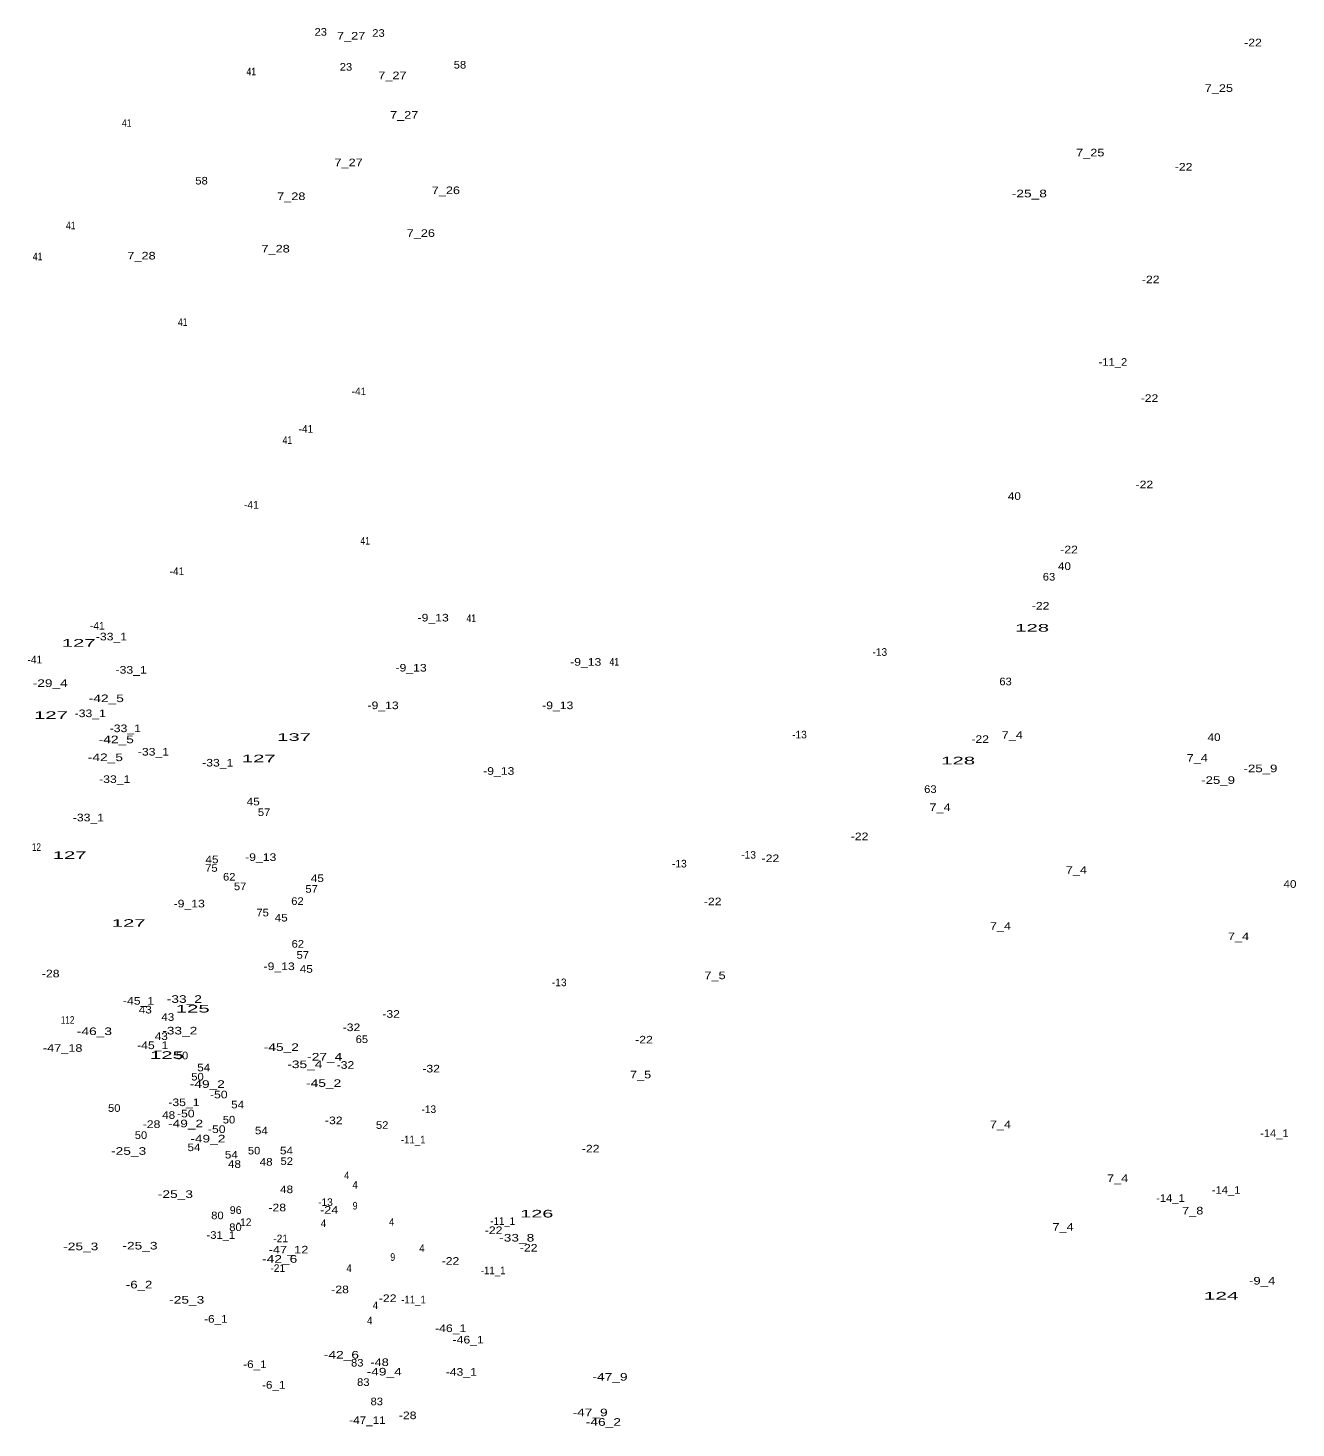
# Model space of a CAD drawing. Extents: x -663705 to -661666, y -1002081 to -999269.
# Drawn here: x -663123 to -662455, y -1001333 to -1000597 of the extents above; entities that cross this region are included whole.
import ezdxf
from ezdxf.enums import TextEntityAlignment as Align

# ---------------------------------------------------------------- set-up
doc = ezdxf.new("R2010")
doc.units = 0
doc.header["$LTSCALE"] = 1.6
doc.layers.add('24', color=7, linetype='Continuous')

msp = doc.modelspace()

# ---------------------------------------------------------------- texts
at = {"layer": '24'}
for s, width, p in [('23', 1.1, (-662968.579, -1000601.17)), ('7_27', 1.25, (-662952.58, -1000603.18)), ('23', 1.1, (-662938.199, -1000601.75)), ('-22', 1.2, (-662478.09, -1000606.76)), ('23', 1.1, (-662955.309, -1000619.54)), ('58', 1.1, (-662895.34, -1000618.45)), ('41', 0.85, (-663005.11, -1000622)), ('7_27', 1.25, (-662930.86, -1000624.04)), ('7_25', 1.25, (-662496.069, -1000630.71)), ('41', 0.85, (-663070.63, -1000649.08)), ('7_27', 1.25, (-662924.66, -1000644.8)), ('7_25', 1.25, (-662563.73, -1000664.65)), ('7_27', 1.25, (-662953.93, -1000669.81)), ('-22', 1.2, (-662514.61, -1000672.14)), ('58', 1.1, (-663031.28, -1000679.42)), ('7_26', 1.25, (-662902.75, -1000684.48)), ('-25_8', 1.35, (-662595.78, -1000686.17)), ('7_28', 1.25, (-662984.079, -1000687.61)), ('41', 0.85, (-663100.1, -1000702.99)), ('7_26', 1.25, (-662915.93, -1000706.98)), ('7_28', 1.25, (-662992.319, -1000715.18)), ('41', 0.85, (-663117.549, -1000719.28)), ('7_28', 1.25, (-663062.88, -1000718.86)), ('-22', 1.2, (-662531.91, -1000731.37)), ('41', 0.85, (-663041.169, -1000753.8)), ('-11_2', 1.1, (-662551.799, -1000774.76)), ('-22', 1.2, (-662532.57, -1000793.8)), ('41', 0.85, (-662986.11, -1000815.86)), ('-22', 1.2, (-662535.26, -1000839.19)), ('40', 1.15, (-662603.669, -1000845.32)), ('41', 0.85, (-662945.199, -1000868.82)), ('-22', 1.2, (-662574.86, -1000873.42)), ('40', 1.15, (-662577.309, -1000882.17)), ('63', 1.1, (-662585.42, -1000887.73)), ('-22', 1.2, (-662589.85, -1000903.03)), ('-9_13', 1.2, (-662909.431, -1000909.26)), ('41', 0.85, (-662889.37, -1000909.55)), ('128', 2, (-662594.297, -1000914.61)), ('127', 2, (-663095.913, -1000922.52)), ('-33_1', 1.2, (-663078.699, -1000919.2)), ('-33_1', 1.2, (-663068.319, -1000936.7)), ('-9_13', 1.2, (-662921.061, -1000935.6)), ('-9_13', 1.2, (-662829.171, -1000932.53)), ('41', 0.85, (-662814.15, -1000932.44)), ('-29_4', 1.35, (-663110.91, -1000943.69)), ('63', 1.1, (-662608.29, -1000942.81)), ('-42_5', 1.35, (-663081.39, -1000951.68)), ('-33_1', 1.2, (-663089.85, -1000959.58)), ('-9_13', 1.2, (-662935.791, -1000955.38)), ('-9_13', 1.2, (-662843.9, -1000955.38)), ('127', 2, (-663110.493, -1000960.51)), ('-42_5', 1.35, (-663076.16, -1000973.3)), ('-33_1', 1.2, (-663071.4, -1000967.47)), ('137', 2, (-662982.623, -1000972.05)), ('-22', 1.2, (-662621.65, -1000973.15)), ('7_4', 1.25, (-662604.77, -1000970.99)), ('40', 1.15, (-662498.6, -1000972.15)), ('-33_1', 1.2, (-663056.6, -1000979.78)), ('-42_5', 1.35, (-663081.88, -1000982.71)), ('-33_1', 1.2, (-663022.76, -1000985.55)), ('127', 2, (-663001.173, -1000983.34)), ('128', 2, (-662633.227, -1000984.44)), ('7_4', 1.25, (-662507.44, -1000983.01)), ('-25_9', 1.3, (-662474.17, -1000988.55)), ('-33_1', 1.2, (-663076.97, -1000994.2)), ('-9_13', 1.2, (-662874.921, -1000989.9)), ('-25_9', 1.3, (-662496.47, -1000994.71)), ('63', 1.1, (-662647.84, -1000999.44)), ('45', 1.15, (-663004.1, -1001005.98)), ('7_4', 1.25, (-662642.76, -1001009)), ('-33_1', 1.2, (-663090.809, -1001014.39)), ('57', 1.1, (-662998.39, -1001011.6)), ('-22', 1.2, (-662685.09, -1001024.3)), ('12', 0.8, (-663118.169, -1001029.94)), ('127', 2, (-663100.713, -1001034.18)), ('45', 1.15, (-663025.809, -1001036.43)), ('-9_13', 1.2, (-663000.16, -1001035.22)), ('-22', 1.2, (-662731.99, -1001035.84)), ('75', 1.1, (-663026.1, -1001040.92)), ('62', 1.1, (-663016.71, -1001045.54)), ('45', 1.15, (-662970.37, -1001046.32)), ('7_4', 1.25, (-662571.03, -1001041.97)), ('57', 1.1, (-663010.99, -1001050.58)), ('57', 1.1, (-662973.38, -1001051.94)), ('40', 1.15, (-662458.66, -1001049.34)), ('-9_13', 1.2, (-663037.77, -1001059.65)), ('62', 1.1, (-662980.84, -1001058.34)), ('-22', 1.2, (-662762.37, -1001058.53)), ('127', 2, (-663069.643, -1001069.87)), ('75', 1.1, (-662999.16, -1001064.39)), ('45', 1.15, (-662989.37, -1001067.07)), ('7_4', 1.25, (-662610.97, -1001071.45)), ('7_4', 1.25, (-662485.73, -1001076.88)), ('62', 1.1, (-662980.65, -1001080.84)), ('57', 1.1, (-662978.03, -1001086.66)), ('-28', 1.2, (-663110.65, -1001096.44)), ('-9_13', 1.2, (-662990.461, -1001092.62)), ('45', 1.15, (-662976.179, -1001094.03)), ('7_5', 1.25, (-662761.15, -1001097.41)), ('-45_1', 1.2, (-663064.439, -1001110.81)), ('-33_2', 1.35, (-663040.34, -1001109.85)), ('112', 0.8, (-663101.77, -1001120.88)), ('43', 1.15, (-663060.89, -1001115.44)), ('43', 1.15, (-663049.059, -1001119.32)), ('125', 2, (-663035.907, -1001114.94)), ('-32', 1.2, (-662931.55, -1001117.71)), ('-46_3', 1.35, (-663087.65, -1001126.8)), ('-33_2', 1.35, (-663042.74, -1001126.48)), ('-32', 1.2, (-662952.41, -1001124.73)), ('-47_18', 1.25, (-663104.36, -1001135.62)), ('-45_1', 1.2, (-663056.98, -1001134.18)), ('43', 1.15, (-663052.449, -1001129.4)), ('-45_2', 1.35, (-662989.33, -1001135.15)), ('65', 1.1, (-662946.95, -1001130.99)), ('-22', 1.2, (-662798.51, -1001131.23)), ('125', 2, (-663049.517, -1001139.31)), ('50', 1.1, (-663041.559, -1001139.55)), ('-27_4', 1.35, (-662966.47, -1001140.21)), ('50', 1.1, (-663033.419, -1001150.71)), ('54', 1.15, (-663030.13, -1001145.85)), ('-35_4', 1.35, (-662976.95, -1001144.19)), ('-32', 1.2, (-662955.58, -1001144.54)), ('-32', 1.2, (-662910.5, -1001146.46)), ('7_5', 1.25, (-662800.309, -1001149.58)), ('-49_2', 1.35, (-663028.26, -1001154.57)), ('-45_2', 1.35, (-662967.04, -1001154.06)), ('-35_1', 1.2, (-663040.569, -1001164.17)), ('-50', 1.2, (-663022.22, -1001160.08)), ('54', 1.15, (-663012.299, -1001165.34)), ('50', 1.1, (-663077.209, -1001167.19)), ('48', 1.15, (-663048.6, -1001170.87)), ('-50', 1.2, (-663039.58, -1001170.07)), ('50', 1.1, (-663016.84, -1001173.3)), ('-28', 1.2, (-663057.59, -1001175.68)), ('-49_2', 1.35, (-663039.7, -1001175.32)), ('-50', 1.2, (-663023.29, -1001178.31)), ('54', 1.15, (-662999.79, -1001179.01)), ('-32', 1.2, (-662961.73, -1001173.67)), ('52', 1.1, (-662936.26, -1001176.12)), ('7_4', 1.25, (-662610.97, -1001175.79)), ('-14_1', 1.1, (-662466.88, -1001180.42)), ('50', 1.1, (-663063.15, -1001181.44)), ('54', 1.15, (-663035.27, -1001187.84)), ('-49_2', 1.35, (-663027.97, -1001183.27)), ('-11_1', 0.95, (-662919.95, -1001183.76)), ('-25_3', 1.35, (-663069.65, -1001189.78)), ('54', 1.15, (-663015.59, -1001191.71)), ('50', 1.1, (-663003.66, -1001189.59)), ('54', 1.15, (-662986.61, -1001189.58)), ('52', 1.1, (-662986.48, -1001195.12)), ('-22', 1.2, (-662826.57, -1001188.53)), ('48', 1.15, (-663013.98, -1001196.66)), ('48', 1.15, (-662997.309, -1001195.5)), ('4', 0.95, (-662954.929, -1001202.59)), ('48', 1.15, (-662986.549, -1001209.95)), ('4', 0.95, (-662950.5, -1001207.59)), ('7_4', 1.25, (-662549.32, -1001204.1)), ('-25_3', 1.35, (-663045.04, -1001212.47)), ('-14_1', 1.1, (-662521.549, -1001214.55)), ('-14_1', 1.1, (-662492.27, -1001210.28)), ('80', 1.1, (-663022.939, -1001223.66)), ('96', 1.05, (-663013.35, -1001220.85)), ('-28', 1.2, (-662991.46, -1001219.52)), ('-24', 1.25, (-662964.16, -1001220.79)), ('9', 0.85, (-662950.51, -1001218.53)), ('126', 1.95, (-662854.913, -1001222.75)), ('7_8', 1.25, (-662509.819, -1001221.16)), ('80', 1.1, (-663013.449, -1001229.87)), ('4', 0.95, (-662967.13, -1001227.79)), ('4', 0.95, (-662931.28, -1001227.11)), ('-22', 1.2, (-662877.63, -1001231.46)), ('-11_1', 0.95, (-662872.84, -1001226.62)), ('7_4', 1.25, (-662578.01, -1001229.7)), ('-25_3', 1.35, (-663063.689, -1001239.58)), ('-31_1', 1.1, (-663021.12, -1001233.98)), ('-33_8', 1.35, (-662865.47, -1001235.4)), ('-25_3', 1.35, (-663094.829, -1001239.96)), ('-42_6', 1.35, (-662990.17, -1001246.56)), ('-47_12', 1.25, (-662985.53, -1001241.67)), ('9', 0.85, (-662930.71, -1001245.55)), ('4', 0.95, (-662915.329, -1001240.86)), ('-22', 1.2, (-662859.18, -1001240.69)), ('4', 0.95, (-662953.669, -1001251.43)), ('-22', 1.2, (-662900.32, -1001247.61)), ('-11_1', 0.95, (-662877.88, -1001252.59)), ('-6_2', 1.3, (-663064.14, -1001260.05)), ('-9_4', 1.3, (-662473.28, -1001258.02)), ('-25_3', 1.35, (-663039.079, -1001268.04)), ('-28', 1.2, (-662958.4, -1001262.6)), ('-22', 1.2, (-662933.38, -1001267.23)), ('-11_1', 0.95, (-662919.76, -1001267.91)), ('124', 2.05, (-662494.833, -1001265.89)), ('4', 0.95, (-662939.84, -1001270.96)), ('-6_1', 1.15, (-663023.75, -1001278.08)), ('4', 0.95, (-662942.809, -1001278.95)), ('-46_1', 1.2, (-662900.22, -1001283.02)), ('-46_1', 1.2, (-662891.01, -1001289.03)), ('-42_6', 1.35, (-662957.7, -1001296.96)), ('-6_1', 1.15, (-663003.201, -1001301.93)), ('83', 1.1, (-662949.38, -1001301.15)), ('-49_4', 1.35, (-662935.189, -1001305.84)), ('-48', 1.25, (-662937.62, -1001300.89)), ('-6_1', 1.15, (-662993.311, -1001312.79)), ('83', 1.1, (-662946.189, -1001311.32)), ('-43_1', 1.2, (-662894.62, -1001305.98)), ('-47_9', 1.35, (-662816.39, -1001308.56)), ('83', 1.1, (-662939.11, -1001321.5)), ('-47_9', 1.35, (-662826.861, -1001327.28)), ('-47_11', 1.15, (-662943.99, -1001331.36)), ('-28', 1.2, (-662922.84, -1001328.83)), ('-46_2', 1.35, (-662819.88, -1001332.32))]:
    msp.add_text(s, height=4, dxfattribs=dict(at, width=width)).set_placement(p, align=Align.CENTER)
for s, p in [('-41', (-662948.47, -1000790.2)), ('-41', (-662976.38, -1000809.98)), ('-41', (-663005.07, -1000849.93)), ('-41', (-663044.24, -1000884.84)), ('-41', (-663086.11, -1000913.54)), ('-13', (-662674.451, -1000927.32)), ('-41', (-663118.97, -1000931.29)), ('-13', (-662716.711, -1000970.76)), ('-13', (-662779.91, -1001038.64)), ('-13', (-662743.461, -1001033.98)), ('-13', (-662843.111, -1001101.09)), ('-13', (-662911.74, -1001167.8)), ('-13', (-662966.111, -1001216.68)), ('-12', (-663008.89, -1001227.25)), ('-21', (-662989.671, -1001235.79)), ('-21', (-662991.201, -1001251.37))]:
    msp.add_text(s, height=4, dxfattribs=at).set_placement(p, align=Align.CENTER)

doc.saveas('drawing.dxf')
